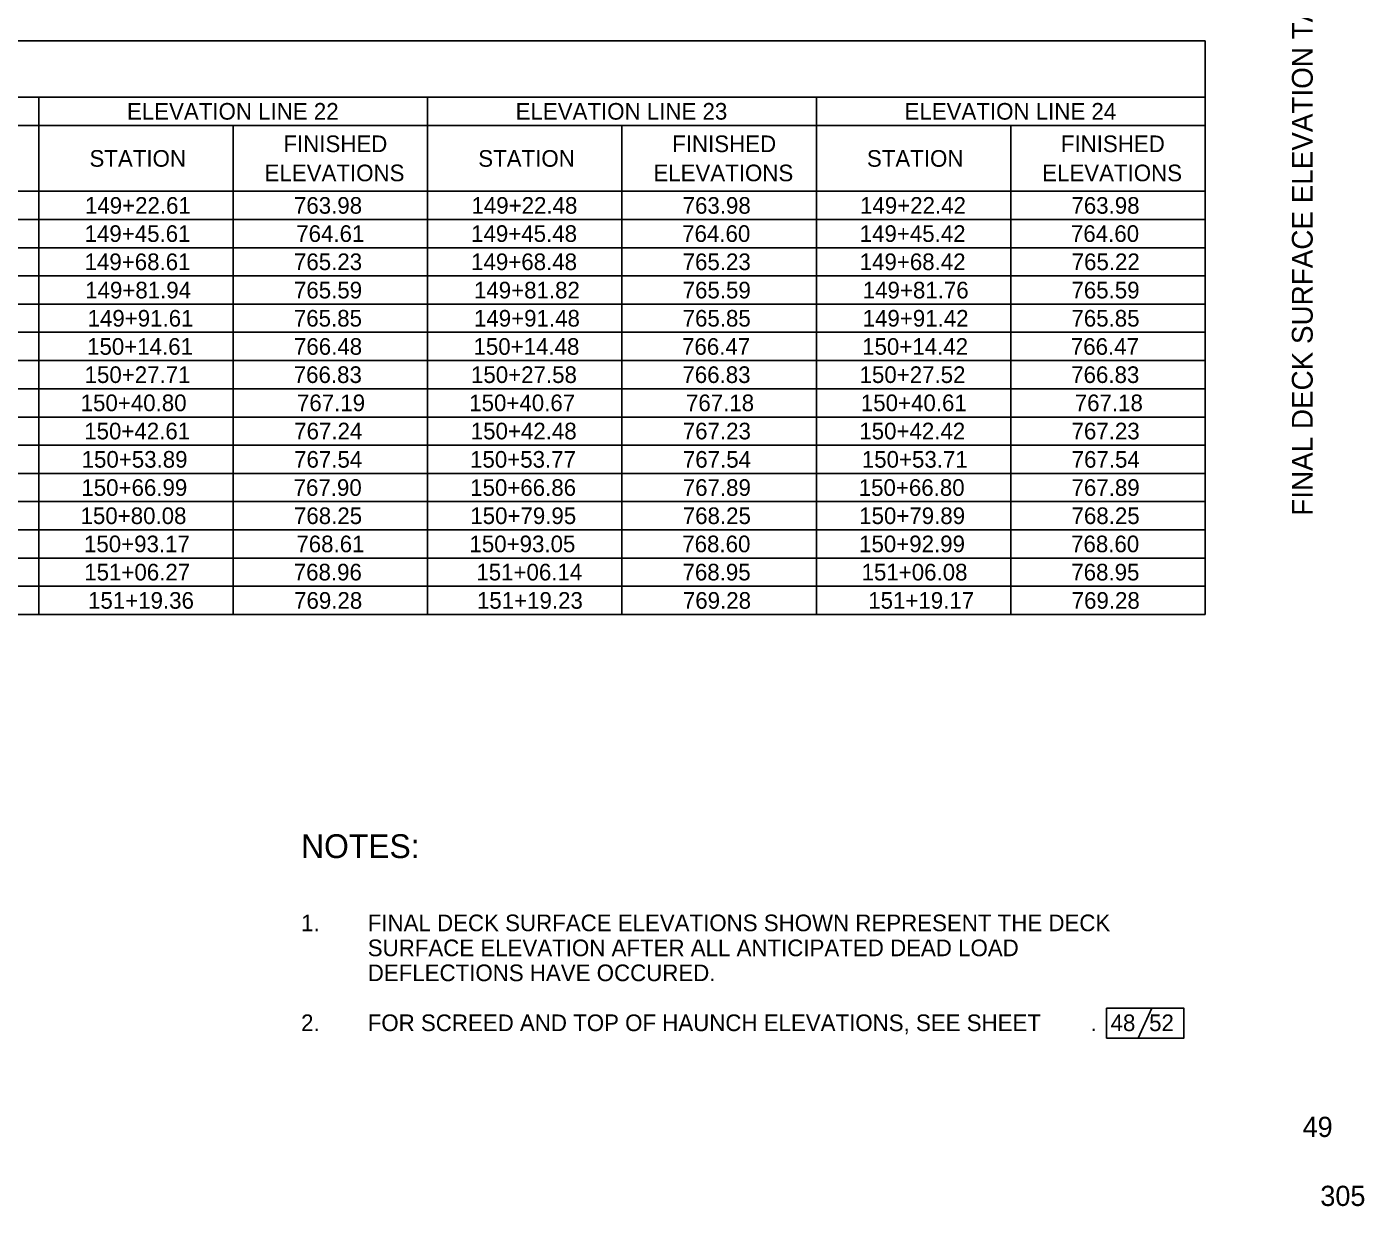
# Model space of a CAD drawing. Extents: x 2.7 to 33.4, y 1.1 to 21.
# Drawn here: x 21.94 to 33.19, y 1.08 to 11 of the extents above; entities that cross this region are included whole.
import ezdxf

# ---------------------------------------------------------------- set-up
doc = ezdxf.new("R2010")
doc.units = 0
for name, color, linetype in [('BR_P_Slab_Text', 7, 'Continuous'), ('BR_X_Beam_Object', 7, 'Continuous'), ('BR_X_Slab_Object', 7, 'Continuous')]:
    doc.layers.add(name, color=color, linetype=linetype)

msp = doc.modelspace()

# ---------------------------------------------------------------- linework, layer by layer
at = {"layer": 'BR_X_Beam_Object'}
msp.add_line((31.403, 2.747), (31.288, 2.497), dxfattribs=at)
msp.add_lwpolyline([(31.021, 2.497), (31.671, 2.497), (31.671, 2.747), (31.021, 2.747)], close=True, dxfattribs=at)
at = {"layer": 'BR_X_Slab_Object'}
for p, q in [((12.243, 10.88), (22.046, 10.88)), ((22.046, 10.88), (28.582, 10.88)), ((28.582, 10.88), (31.85, 10.88)), ((31.85, 10.88), (31.85, 10.643)), ((31.85, 10.643), (31.85, 8.904)), ((12.243, 10.406), (22.046, 10.406)), ((22.046, 10.406), (28.582, 10.406)), ((22.046, 10.406), (22.046, 8.904)), ((25.314, 10.406), (25.314, 8.904)), ((28.582, 10.406), (31.85, 10.406)), ((28.582, 10.406), (28.582, 8.904)), ((12.243, 10.169), (22.046, 10.169)), ((22.046, 10.169), (28.582, 10.169)), ((23.68, 10.169), (23.68, 8.904)), ((26.948, 10.169), (26.948, 8.904)), ((28.582, 10.169), (31.85, 10.169)), ((30.216, 10.169), (30.216, 8.904)), ((12.243, 9.616), (22.046, 9.616)), ((22.046, 9.616), (28.582, 9.616)), ((28.582, 9.616), (31.85, 9.616)), ((12.243, 9.378), (22.046, 9.378)), ((22.046, 9.378), (28.582, 9.378)), ((28.582, 9.378), (31.85, 9.378)), ((12.243, 9.141), (22.046, 9.141)), ((22.046, 9.141), (28.582, 9.141)), ((28.582, 9.141), (31.85, 9.141)), ((12.243, 8.904), (22.046, 8.904)), ((22.046, 8.904), (28.582, 8.904)), ((22.046, 8.904), (22.046, 8.43)), ((23.68, 8.904), (23.68, 8.43)), ((25.314, 8.904), (25.314, 8.43)), ((26.948, 8.904), (26.948, 8.43)), ((28.582, 8.904), (31.85, 8.904)), ((28.582, 8.904), (28.582, 8.43)), ((30.216, 8.904), (30.216, 8.43)), ((31.85, 8.904), (31.85, 8.43)), ((12.243, 8.667), (22.046, 8.667)), ((22.046, 8.667), (28.582, 8.667)), ((28.582, 8.667), (31.85, 8.667)), ((12.243, 8.43), (22.046, 8.43)), ((22.046, 8.43), (28.582, 8.43)), ((22.046, 8.43), (22.046, 7.718)), ((23.68, 8.43), (23.68, 7.718)), ((25.314, 8.43), (25.314, 7.718)), ((26.948, 8.43), (26.948, 7.718)), ((28.582, 8.43), (31.85, 8.43)), ((28.582, 8.43), (28.582, 7.718)), ((30.216, 8.43), (30.216, 7.718)), ((31.85, 8.43), (31.85, 7.718)), ((12.243, 8.192), (22.046, 8.192)), ((22.046, 8.192), (28.582, 8.192)), ((28.582, 8.192), (31.85, 8.192)), ((12.243, 7.955), (22.046, 7.955)), ((22.046, 7.955), (28.582, 7.955)), ((28.582, 7.955), (31.85, 7.955)), ((12.243, 7.718), (22.046, 7.718)), ((22.046, 7.718), (28.582, 7.718)), ((22.046, 7.718), (22.046, 7.244)), ((23.68, 7.718), (23.68, 7.244)), ((25.314, 7.718), (25.314, 7.244)), ((26.948, 7.718), (26.948, 7.244)), ((28.582, 7.718), (31.85, 7.718)), ((28.582, 7.718), (28.582, 7.244)), ((30.216, 7.718), (30.216, 7.244)), ((31.85, 7.718), (31.85, 7.244)), ((12.243, 7.481), (22.046, 7.481)), ((22.046, 7.481), (28.582, 7.481)), ((28.582, 7.481), (31.85, 7.481)), ((12.243, 7.244), (22.046, 7.244)), ((22.046, 7.244), (28.582, 7.244)), ((22.046, 7.244), (22.046, 6.532)), ((23.68, 7.244), (23.68, 6.532)), ((25.314, 7.244), (25.314, 6.532)), ((26.948, 7.244), (26.948, 6.532)), ((28.582, 7.244), (31.85, 7.244)), ((28.582, 7.244), (28.582, 6.532)), ((30.216, 7.244), (30.216, 6.532)), ((31.85, 7.244), (31.85, 6.532)), ((12.243, 7.007), (22.046, 7.007)), ((22.046, 7.007), (28.582, 7.007)), ((28.582, 7.007), (31.85, 7.007)), ((12.243, 6.769), (22.046, 6.769)), ((22.046, 6.769), (28.582, 6.769)), ((28.582, 6.769), (31.85, 6.769)), ((12.243, 6.532), (22.046, 6.532)), ((22.046, 6.532), (28.582, 6.532)), ((22.046, 6.532), (22.046, 6.058)), ((23.68, 6.532), (23.68, 6.058)), ((25.314, 6.532), (25.314, 6.058)), ((26.948, 6.532), (26.948, 6.058)), ((28.582, 6.532), (31.85, 6.532)), ((28.582, 6.532), (28.582, 6.058)), ((30.216, 6.532), (30.216, 6.058)), ((31.85, 6.532), (31.85, 6.058)), ((12.243, 6.295), (22.046, 6.295)), ((22.046, 6.295), (28.582, 6.295)), ((28.582, 6.295), (31.85, 6.295)), ((12.243, 6.058), (22.046, 6.058)), ((22.046, 6.058), (28.582, 6.058)), ((28.582, 6.058), (31.85, 6.058))]:
    msp.add_line(p, q, dxfattribs=at)

# ---------------------------------------------------------------- texts
at = {"layer": 'BR_P_Slab_Text'}
for s, height, p in [('48', 0.14, (31.055, 2.555)), ('52', 0.14, (31.379, 2.555)), ('49', 0.17, (32.669, 1.665)), ('305', 0.17, (32.818, 1.085))]:
    msp.add_text(s, height=height, dxfattribs=at).set_placement(p)
at = {"layer": 'BR_X_Beam_Object'}
for s, height, p in [('ELEVATION LINE 22', 0.14, (22.787, 10.218)), ('ELEVATION LINE 23', 0.14, (26.054, 10.218)), ('ELEVATION LINE 24', 0.14, (29.323, 10.218)), ('FINISHED', 0.14, (24.102, 9.945)), ('FINISHED', 0.14, (27.37, 9.945)), ('FINISHED', 0.14, (30.637, 9.945)), ('STATION', 0.14, (22.472, 9.822)), ('STATION', 0.14, (25.74, 9.822)), ('STATION', 0.14, (29.007, 9.822)), ('ELEVATIONS', 0.14, (23.944, 9.7)), ('ELEVATIONS', 0.14, (27.212, 9.7)), ('ELEVATIONS', 0.14, (30.48, 9.7)), ('149+22.61', 0.14, (22.434, 9.427)), ('763.98', 0.14, (24.191, 9.427)), ('149+22.48', 0.14, (25.683, 9.427)), ('763.98', 0.14, (27.458, 9.427)), ('149+22.42', 0.14, (28.949, 9.427)), ('763.98', 0.14, (30.726, 9.427)), ('149+45.61', 0.14, (22.431, 9.19)), ('764.61', 0.14, (24.21, 9.19)), ('149+45.48', 0.14, (25.68, 9.19)), ('764.60', 0.14, (27.454, 9.19)), ('149+45.42', 0.14, (28.946, 9.19)), ('764.60', 0.14, (30.722, 9.19)), ('149+68.61', 0.14, (22.431, 8.953)), ('765.23', 0.14, (24.191, 8.953)), ('149+68.48', 0.14, (25.68, 8.953)), ('765.23', 0.14, (27.458, 8.953)), ('149+68.42', 0.14, (28.946, 8.953)), ('765.22', 0.14, (30.728, 8.953)), ('149+81.94', 0.14, (22.436, 8.715)), ('765.59', 0.14, (24.191, 8.715)), ('149+81.82', 0.14, (25.704, 8.715)), ('765.59', 0.14, (27.458, 8.715)), ('149+81.76', 0.14, (28.972, 8.715)), ('765.59', 0.14, (30.726, 8.715)), ('149+91.61', 0.14, (22.456, 8.478)), ('765.85', 0.14, (24.19, 8.478)), ('149+91.48', 0.14, (25.704, 8.478)), ('765.85', 0.14, (27.458, 8.478)), ('149+91.42', 0.14, (28.971, 8.478)), ('765.85', 0.14, (30.726, 8.478)), ('150+14.61', 0.14, (22.452, 8.241)), ('766.48', 0.14, (24.191, 8.241)), ('150+14.48', 0.14, (25.7, 8.241)), ('766.47', 0.14, (27.453, 8.241)), ('150+14.42', 0.14, (28.967, 8.241)), ('766.47', 0.14, (30.721, 8.241)), ('150+27.71', 0.14, (22.431, 8.004)), ('766.83', 0.14, (24.189, 8.004)), ('150+27.58', 0.14, (25.679, 8.004)), ('766.83', 0.14, (27.456, 8.004)), ('150+27.52', 0.14, (28.945, 8.004)), ('766.83', 0.14, (30.724, 8.004)), ('150+40.80', 0.14, (22.398, 7.767)), ('767.19', 0.14, (24.216, 7.767)), ('150+40.67', 0.14, (25.664, 7.767)), ('767.18', 0.14, (27.486, 7.767)), ('150+40.61', 0.14, (28.956, 7.767)), ('767.18', 0.14, (30.754, 7.767)), ('150+42.61', 0.14, (22.428, 7.53)), ('767.24', 0.14, (24.193, 7.53)), ('150+42.48', 0.14, (25.677, 7.53)), ('767.23', 0.14, (27.459, 7.53)), ('150+42.42', 0.14, (28.943, 7.53)), ('767.23', 0.14, (30.727, 7.53)), ('150+53.89', 0.14, (22.406, 7.292)), ('767.54', 0.14, (24.192, 7.292)), ('150+53.77', 0.14, (25.671, 7.292)), ('767.54', 0.14, (27.46, 7.292)), ('150+53.71', 0.14, (28.964, 7.292)), ('767.54', 0.14, (30.728, 7.292)), ('150+66.99', 0.14, (22.404, 7.055)), ('767.90', 0.14, (24.188, 7.055)), ('150+66.86', 0.14, (25.672, 7.055)), ('767.89', 0.14, (27.459, 7.055)), ('150+66.80', 0.14, (28.938, 7.055)), ('767.89', 0.14, (30.727, 7.055)), ('150+80.08', 0.14, (22.397, 6.818)), ('768.25', 0.14, (24.191, 6.818)), ('150+79.95', 0.14, (25.673, 6.818)), ('768.25', 0.14, (27.459, 6.818)), ('150+79.89', 0.14, (28.942, 6.818)), ('768.25', 0.14, (30.727, 6.818)), ('150+93.17', 0.14, (22.426, 6.581)), ('768.61', 0.14, (24.211, 6.581)), ('150+93.05', 0.14, (25.666, 6.581)), ('768.60', 0.14, (27.455, 6.581)), ('150+92.99', 0.14, (28.941, 6.581)), ('768.60', 0.14, (30.723, 6.581)), ('151+06.27', 0.14, (22.428, 6.344)), ('768.96', 0.14, (24.189, 6.344)), ('151+06.14', 0.14, (25.724, 6.344)), ('768.95', 0.14, (27.457, 6.344)), ('151+06.08', 0.14, (28.962, 6.344)), ('768.95', 0.14, (30.725, 6.344)), ('151+19.36', 0.14, (22.46, 6.106)), ('769.28', 0.14, (24.192, 6.106)), ('151+19.23', 0.14, (25.729, 6.106)), ('769.28', 0.14, (27.46, 6.106)), ('151+19.17', 0.14, (29.018, 6.106)), ('769.28', 0.14, (30.728, 6.106)), ('NOTES:', 0.2, (24.251, 4.01)), ('1.', 0.14, (24.251, 3.395)), ('FINAL DECK SURFACE ELEVATIONS SHOWN REPRESENT THE DECK ', 0.14, (24.811, 3.395)), ('SURFACE ELEVATION AFTER ALL ANTICIPATED DEAD LOAD ', 0.14, (24.811, 3.185)), ('DEFLECTIONS HAVE OCCURED.', 0.14, (24.811, 2.975)), ('2.', 0.14, (24.251, 2.555)), ('FOR SCREED AND TOP OF HAUNCH ELEVATIONS, SEE SHEET        .', 0.14, (24.811, 2.555))]:
    msp.add_text(s, height=height, dxfattribs=at).set_placement(p)
at = {"layer": 'BR_X_Slab_Object'}
msp.add_text('FINAL DECK SURFACE ELEVATION TABLES', height=0.175, rotation=90, dxfattribs=at).set_placement((32.754, 6.888))

doc.saveas('drawing.dxf')
